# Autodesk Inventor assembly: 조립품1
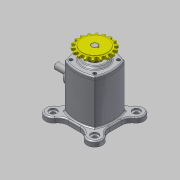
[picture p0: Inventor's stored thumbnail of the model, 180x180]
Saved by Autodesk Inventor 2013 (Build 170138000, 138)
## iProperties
Created: 2016-05
Part Number: 조립품1
Document SubType Name: Assembly
Designer: dgall
Author: dgall
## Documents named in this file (11)
- C:\Users\dgall\Desktop\460507V1027\조립품1.iam
- C:\Users\dgall\Desktop\460507V1027\본체.ipt
- C:\Users\dgall\Desktop\460507V1027\편심축.ipt
- C:\Users\dgall\Desktop\460507V1027\커버.ipt
- C:\Users\dgall\Desktop\460507V1027\오일실.ipt
- C:\Users\dgall\Desktop\460507V1027\베어링-6203.ipt
- C:\Users\dgall\Desktop\460507V1027\스프로킷.ipt
- C:\Users\dgall\Desktop\460507V1027\키5x5.ipt
- C:\Users\dgall\Desktop\460507V1027\부시.ipt
- C:\Users\dgall\Desktop\460507V1027\슬라이더.ipt
- C:\Users\dgall\Desktop\460507V1027\M4x0.7x12.ipt
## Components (8 placed, 1 different names)
1. M4x0.7x12:2
2. M4x0.7x12:3
3. M4x0.7x12:4
4. M4x0.7x12:5
5. M4x0.7x12:1
6. M4x0.7x12:6
7. M4x0.7x12:7
8. M4x0.7x12:8
